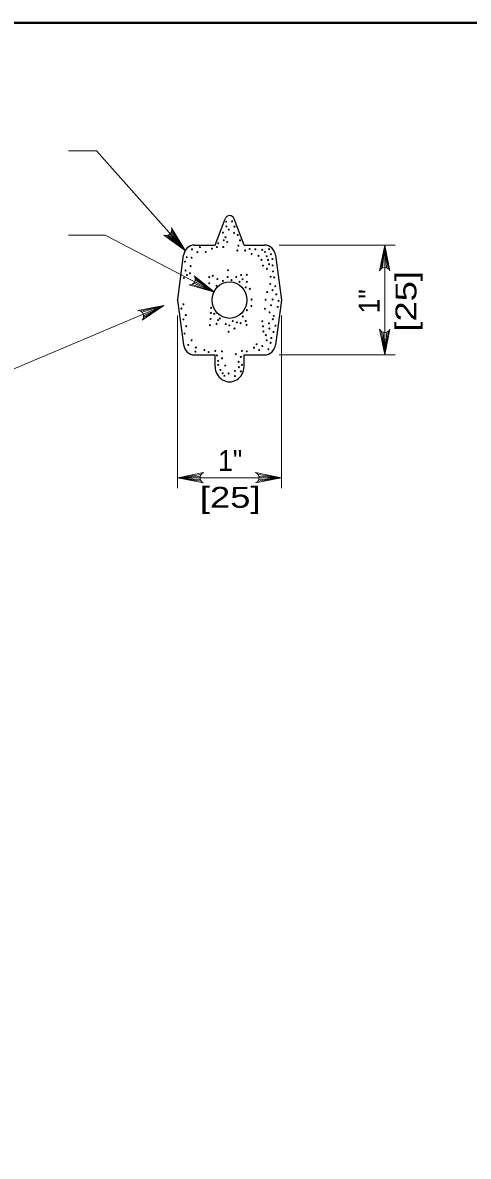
# Model space of a CAD drawing. Extents: x 1083.1 to 1117.1, y 697.4 to 741.4.
# Drawn here: x 1099.22 to 1102.54, y 710.4 to 718.85 of the extents above; entities that cross this region are included whole.
import ezdxf
from ezdxf.enums import TextEntityAlignment as Align

# ---------------------------------------------------------------- set-up
doc = ezdxf.new("R2010")
doc.units = 0
doc.header["$LTSCALE"] = 0.062
doc.layers.add('1', color=7, linetype='Continuous', lineweight=13)

msp = doc.modelspace()

# ---------------------------------------------------------------- linework, layer by layer
at = {"layer": '1', "lineweight": 25}
for p, q in [((1085.12642, 718.85408), (1116.62642, 718.85408)), ((1100.6535, 717.19525), (1100.72758, 717.39)), ((1100.86967, 717.19525), (1100.79558, 717.39)), ((1100.50017, 717.19525), (1100.6535, 717.19525)), ((1100.86967, 717.19525), (1101.02308, 717.19525)), ((1100.37417, 716.78467), (1100.41842, 716.45008)), ((1100.50008, 716.37483), (1100.6535, 716.37483)), ((1100.6535, 716.28908), (1100.6535, 716.37483)), ((1100.86967, 716.28908), (1100.86967, 716.37483)), ((1100.86967, 716.37483), (1101.02308, 716.37483))]:
    msp.add_line(p, q, dxfattribs=at)
at = {"layer": '1'}
for p, q in [((1099.55975, 717.26867), (1099.83458, 717.26867)), ((1100.65017, 716.84283), (1099.83458, 717.26867)), ((1100.29392, 717.26592), (1100.4315, 717.15508)), ((1100.30675, 717.26983), (1100.4315, 717.15508)), ((1100.317, 717.277), (1100.4315, 717.15508)), ((1100.32633, 717.29), (1100.4315, 717.15508)), ((1100.33008, 717.30267), (1100.4315, 717.15508)), ((1101.13242, 717.19525), (1101.99767, 717.19525)), ((1101.892, 717.01817), (1101.919, 717.19525)), ((1101.90333, 717.02492), (1101.919, 717.19525)), ((1101.919, 717.028), (1101.919, 717.19525)), ((1101.93142, 717.02617), (1101.919, 717.19525)), ((1101.9435, 717.02025), (1101.919, 717.19525)), ((1101.919, 716.37483), (1101.919, 717.19525)), ((1100.48358, 716.90167), (1100.65017, 716.84283)), ((1100.49442, 716.90967), (1100.65017, 716.84283)), ((1100.50167, 716.91983), (1100.65017, 716.84283)), ((1100.50542, 716.94833), (1100.65017, 716.84283)), ((1100.50617, 716.93525), (1100.65017, 716.84283)), ((1096.40283, 715.10667), (1100.27158, 716.74517)), ((1100.09792, 716.70133), (1100.27158, 716.74517)), ((1100.1085, 716.6935), (1100.27158, 716.74517)), ((1100.11742, 716.68017), (1100.27158, 716.74517)), ((1100.11983, 716.65467), (1100.27158, 716.74517)), ((1100.12058, 716.66808), (1100.27158, 716.74517)), ((1100.37417, 716.66892), (1100.37417, 715.38058)), ((1101.149, 716.66892), (1101.149, 715.38058)), ((1101.94608, 716.55192), (1101.919, 716.37483)), ((1101.89458, 716.54983), (1101.919, 716.37483)), ((1101.90667, 716.54392), (1101.919, 716.37483)), ((1101.93475, 716.54517), (1101.919, 716.37483)), ((1101.919, 716.54208), (1101.919, 716.37483)), ((1101.13242, 716.37483), (1101.99767, 716.37483)), ((1100.54917, 715.48375), (1100.37417, 715.45925)), ((1100.54325, 715.47167), (1100.37417, 715.45925)), ((1100.54142, 715.45925), (1100.37417, 715.45925)), ((1100.5445, 715.44358), (1100.37417, 715.45925)), ((1100.55125, 715.43217), (1100.37417, 715.45925)), ((1100.37417, 715.45925), (1101.149, 715.45925)), ((1100.97192, 715.43217), (1101.149, 715.45925)), ((1100.974, 715.48375), (1101.149, 715.45925)), ((1100.97867, 715.44358), (1101.149, 715.45925)), ((1100.97992, 715.47167), (1101.149, 715.45925)), ((1100.98175, 715.45925), (1101.149, 715.45925))]:
    msp.add_line(p, q, dxfattribs=at)
at = {"layer": '1', "lineweight": 40}
msp.add_lwpolyline([(1085.12642, 718.85408), (1116.62642, 718.85408), (1116.62642, 697.85408), (1085.12642, 697.85408)], close=True, dxfattribs=at)
at = {"layer": '1'}
for points in [[(1100.4315, 717.15508), (1099.76933, 717.89833), (1099.55975, 717.89833)], [(1100.32742, 717.32242), (1100.4315, 717.15508), (1100.271, 717.2695)], [(1101.88042, 717.00192), (1101.919, 717.19525), (1101.95767, 717.00192)], [(1100.49642, 716.96617), (1100.65017, 716.84283), (1100.46075, 716.8975)], [(1100.07842, 716.70575), (1100.27158, 716.74517), (1100.1085, 716.6345)], [(1101.95767, 716.56817), (1101.919, 716.37483), (1101.88042, 716.56817)], [(1100.5675, 715.42058), (1100.37417, 715.45925), (1100.5675, 715.49792)], [(1100.95567, 715.42058), (1101.149, 715.45925), (1100.95567, 715.49792)]]:
    msp.add_lwpolyline(points, dxfattribs=at)
at = {"layer": '1', "lineweight": 25}
for points in [[(1100.37417, 716.78467), (1100.37458, 716.78775), (1100.41842, 717.12)], [(1101.10475, 717.12), (1101.149, 716.78467), (1101.10475, 716.45008)]]:
    msp.add_lwpolyline(points, dxfattribs=at)
at = {"layer": '1'}
for centre, start, end in [((1100.28849, 717.30734), 245.29036, 21.11649), ((1101.91908, 716.98633), 22.08782, 157.91395), ((1100.4647, 716.93897), 264.67864, 40.50477), ((1100.0791, 716.66399), 314.93944, 90.76557), ((1101.91899, 716.58375), 202.08782, 337.91395), ((1100.58309, 715.45931), 112.08782, 247.91395), ((1100.94009, 715.45931), 292.08605, 67.91218)]:
    msp.add_arc(centre, 0.04172, start, end, dxfattribs=at)
at = {"layer": '1', "lineweight": 25}
for centre, major_axis, start_param, end_param in [((1100.76159, 717.37549), (0, -0.03881), 1.9537157, 4.3294696), ((1100.50013, 717.10792), (0, 0.08731), 6.2831853, 7.7151123), ((1101.02305, 717.10792), (0, 0.08731), 4.8512583, 6.2831853), ((1100.50012, 716.46217), (0, -0.08731), 4.8515066, 6.2831853), ((1101.02306, 716.46217), (0, -0.08731), 6.2831853, 7.7148641), ((1100.76159, 716.28909), (0, 0.11444), 1.5707963, 4.712389)]:
    msp.add_ellipse(centre, major_axis=major_axis, ratio=0.944544, start_param=start_param, end_param=end_param, dxfattribs=at)
at = {"layer": '1'}
for centre, major_axis in [((1100.73621, 717.3687), (0, 0.00358)), ((1100.73779, 717.3342), (0, 0.00409)), ((1100.75577, 717.30997), (0, 0.00409)), ((1100.78072, 717.37175), (0, 0.00409)), ((1100.79828, 717.33247), (0, 0.00409)), ((1100.71164, 717.28748), (0, 0.00409)), ((1100.71818, 717.23036), (0, 0.00409)), ((1100.73126, 717.25286), (0, 0.00409)), ((1100.79501, 717.28575), (0, 0.00409)), ((1100.8228, 717.27017), (0, 0.00409)), ((1100.83914, 717.23036), (0, 0.00409)), ((1100.48115, 717.16287), (0, 0.00409)), ((1100.52202, 717.1421), (0, 0.00409)), ((1100.54, 717.18018), (0, 0.00409)), ((1100.58414, 717.14383), (0, 0.00409)), ((1100.62991, 717.16806), (0, 0.00409)), ((1100.6675, 717.18018), (0, 0.00409)), ((1100.67731, 717.20787), (0, 0.00409)), ((1100.71491, 717.18018), (0, 0.00409)), ((1100.74433, 717.21825), (0, 0.00409)), ((1100.81953, 717.15422), (0, 0.00409)), ((1100.8277, 717.19056), (0, 0.00409)), ((1100.87674, 717.15422), (0, 0.00409)), ((1100.91107, 717.16633), (0, 0.00409)), ((1100.95357, 717.16287), (0, 0.00409)), ((1101.00588, 717.15941), (0, 0.00409)), ((1101.02549, 717.14383), (0, 0.00409)), ((1101.05655, 717.1646), (0, 0.00409)), ((1100.42884, 717.07115), (0, 0.00409)), ((1100.44192, 717.10403), (0, 0.00409)), ((1100.47788, 717.10057), (0, 0.00409)), ((1100.92578, 717.12826), (0, 0.00409)), ((1100.97809, 717.11441), (0, 0.00409)), ((1100.99934, 717.08499), (0, 0.00409)), ((1101.03857, 717.11095), (0, 0.00409)), ((1101.04838, 717.08326), (0, 0.00409)), ((1101.06963, 717.12653), (0, 0.00409)), ((1101.08107, 717.09018), (0, 0.00409)), ((1100.43375, 717.00538), (0, 0.00409)), ((1100.44355, 716.97077), (0, 0.00409)), ((1100.46644, 716.98461), (0, 0.00409)), ((1100.47134, 717.03826), (0, 0.00409)), ((1100.75087, 717.00711), (0, 0.00409)), ((1100.84732, 716.97077), (0, 0.00409)), ((1100.88982, 716.9725), (0, 0.00409)), ((1101.01078, 717.04172), (0, 0.00409)), ((1101.04021, 717.0175), (0, 0.00409)), ((1101.05655, 717.05211), (0, 0.00409)), ((1101.08271, 717.04346), (0, 0.00409)), ((1101.08598, 716.99846), (0, 0.00409)), ((1100.42067, 716.95), (0, 0.00409)), ((1100.61029, 716.95519), (0, 0.00409)), ((1100.61029, 716.9102), (0, 0.00409)), ((1100.63644, 716.96558), (0, 0.00409)), ((1100.66423, 716.89116), (0, 0.00409)), ((1100.67077, 716.94135), (0, 0.00409)), ((1100.71164, 716.9275), (0, 0.00409)), ((1100.7476, 716.95693), (0, 0.00409)), ((1100.77539, 716.9327), (0, 0.00409)), ((1100.81135, 716.95693), (0, 0.00409)), ((1100.83587, 716.92058), (0, 0.00409)), ((1100.85876, 716.93962), (0, 0.00409)), ((1100.88982, 716.92058), (0, 0.00409)), ((1101.06473, 716.90501), (0, 0.00409)), ((1101.068, 716.95865), (0, 0.00409)), ((1101.09415, 716.95346), (0, 0.00409)), ((1101.10232, 716.8877), (0, 0.00409)), ((1100.88164, 716.87905), (0, 0.00409)), ((1100.9127, 716.86866), (0, 0.00409)), ((1101.04184, 716.84443), (0, 0.00409)), ((1101.08271, 716.85828), (0, 0.00409)), ((1101.1105, 716.82713), (0, 0.00409)), ((1100.40269, 716.72156), (0, 0.00409)), ((1100.4174, 716.75271), (0, 0.00409)), ((1100.62337, 716.72675), (0, 0.00409)), ((1100.92414, 716.7406), (0, 0.00409)), ((1100.92578, 716.78905), (0, 0.00409)), ((1101.02549, 716.71983), (0, 0.00409)), ((1101.0304, 716.78732), (0, 0.00409)), ((1101.07126, 716.74579), (0, 0.00409)), ((1101.08271, 716.78905), (0, 0.00409)), ((1101.1203, 716.73367), (0, 0.00409)), ((1101.12684, 716.77867), (0, 0.00409)), ((1100.4174, 716.64022), (0, 0.00409)), ((1100.43538, 716.6731), (0, 0.00409)), ((1100.6201, 716.64368), (0, 0.00409)), ((1100.62173, 716.68868), (0, 0.00409)), ((1100.64789, 716.68175), (0, 0.00409)), ((1100.67568, 716.63503), (0, 0.00409)), ((1100.68875, 716.64714), (0, 0.00409)), ((1100.86039, 716.66272), (0, 0.00409)), ((1100.89145, 716.70944), (0, 0.00409)), ((1101.05982, 716.69214), (0, 0.00409)), ((1101.08434, 716.64195), (0, 0.00409)), ((1101.09088, 716.66618), (0, 0.00409)), ((1100.43865, 716.59003), (0, 0.00409)), ((1100.61519, 716.59695), (0, 0.00409)), ((1100.66423, 716.60734), (0, 0.00409)), ((1100.73289, 716.6056), (0, 0.00409)), ((1100.75414, 716.54849), (0, 0.00409)), ((1100.76068, 716.59522), (0, 0.00409)), ((1100.7852, 716.6281), (0, 0.00409)), ((1100.79828, 716.57272), (0, 0.00409)), ((1100.81626, 716.61772), (0, 0.00409)), ((1100.84405, 716.61253), (0, 0.00409)), ((1100.88164, 716.6281), (0, 0.00409)), ((1100.88818, 716.59868), (0, 0.00409)), ((1101.00588, 716.62637), (0, 0.00409)), ((1101.01078, 716.5883), (0, 0.00409)), ((1101.01405, 716.55023), (0, 0.00409)), ((1101.05492, 716.6108), (0, 0.00409)), ((1101.05819, 716.57272), (0, 0.00409)), ((1101.10396, 716.59349), (0, 0.00409)), ((1100.42557, 716.53465), (0, 0.00409)), ((1100.47788, 716.48446), (0, 0.00409)), ((1101.03203, 716.52253), (0, 0.00409)), ((1101.03857, 716.48446), (0, 0.00409)), ((1101.068, 716.46542), (0, 0.00409)), ((1101.0729, 716.50177), (0, 0.00409)), ((1101.08925, 716.54676), (0, 0.00409)), ((1100.45336, 716.44985), (0, 0.00409)), ((1100.50731, 716.39966), (0, 0.00409)), ((1100.51058, 716.43081), (0, 0.00409)), ((1100.57433, 716.41177), (0, 0.00409)), ((1100.60539, 716.3962), (0, 0.00409)), ((1100.65443, 716.40485), (0, 0.00409)), ((1100.7051, 716.40139), (0, 0.00409)), ((1100.80808, 716.38062), (0, 0.00409)), ((1100.85386, 716.40485), (0, 0.00409)), ((1100.88982, 716.40139), (0, 0.00409)), ((1100.94376, 716.42908), (0, 0.00409)), ((1100.96338, 716.45504), (0, 0.00409)), ((1100.98136, 716.41177), (0, 0.00409)), ((1101.00588, 716.44119), (0, 0.00409)), ((1101.05165, 716.41697), (0, 0.00409)), ((1100.6675, 716.37197), (0, 0.00409)), ((1100.67568, 716.33043), (0, 0.00409)), ((1100.67731, 716.30101), (0, 0.00409)), ((1100.7051, 716.34947), (0, 0.00409)), ((1100.72962, 716.29582), (0, 0.00409)), ((1100.82934, 716.32351), (0, 0.00409)), ((1100.84568, 716.35986), (0, 0.00409)), ((1100.85386, 716.30101), (0, 0.00409)), ((1100.69366, 716.26294), (0, 0.00409)), ((1100.71001, 716.23871), (0, 0.00409)), ((1100.72308, 716.21967), (0, 0.00409)), ((1100.75414, 716.23698), (0, 0.00409)), ((1100.80154, 716.25602), (0, 0.00409)), ((1100.80154, 716.21794), (0, 0.00409)), ((1100.83097, 716.28371), (0, 0.00409)), ((1100.84568, 716.25256), (0, 0.00409))]:
    msp.add_ellipse(centre, major_axis=major_axis, ratio=0.944544, dxfattribs=at)
at = {"layer": '1', "lineweight": 25}
msp.add_ellipse((1100.76159, 716.78467), major_axis=(0, -0.1367), ratio=0.944544, dxfattribs=at)

# ---------------------------------------------------------------- texts
at = {"layer": '1'}
for s, width, p in [('[25]', 1.3, (1102.15508, 716.77504)), ('1"', 0.95, (1101.88108, 716.77504))]:
    msp.add_text(s, height=0.156, rotation=90, dxfattribs=dict(at, width=width)).set_placement(p, align=Align.CENTER)
for s, width, p in [('1"', 0.95, (1100.76629, 715.50908)), ('[25]', 1.3, (1100.76629, 715.23508))]:
    msp.add_text(s, height=0.156, dxfattribs=dict(at, width=width)).set_placement(p, align=Align.CENTER)

doc.saveas('drawing.dxf')
